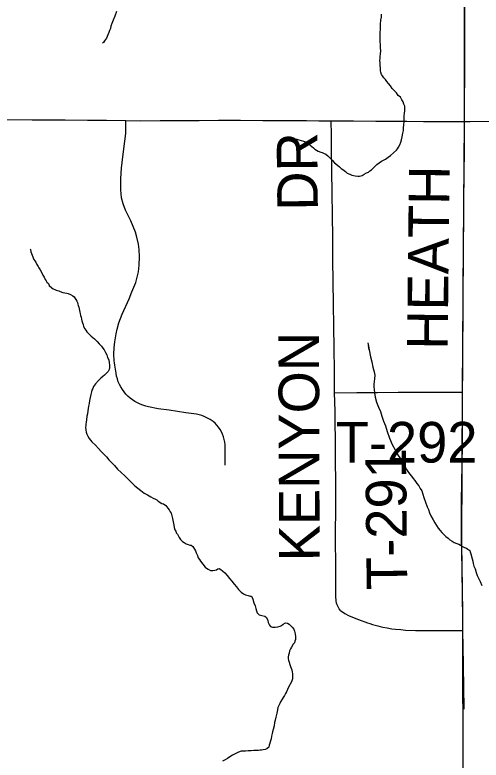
# Model space of a CAD drawing. Extents: x 103424 to 290657, y 38711 to 110967.
# Drawn here: x 116302 to 119767, y 74147 to 79687 of the extents above; entities that cross this region are included whole.
import ezdxf

# ---------------------------------------------------------------- set-up
doc = ezdxf.new("R2010")
doc.units = 0
for name, color, linetype in [('GM_X_Corporation', 7, 'Continuous'), ('GM_X_Minor_River', 7, 'Continuous'), ('GM_X_Township_Road', 7, 'Continuous'), ('GM_X_Township_Road_Text', 7, 'Continuous'), ('GM_X_US_Route', 7, 'Continuous'), ('SC_Scratch1', 7, 'Continuous')]:
    doc.layers.add(name, color=color, linetype=linetype)

msp = doc.modelspace()

# ---------------------------------------------------------------- linework, layer by layer
at = {"layer": 'GM_X_Corporation'}
for points in [[(103423.7, 96534.8), (103423.7, 70904.9), (107977, 70917.3), (117928.9, 70934.4), (117946.9, 70934.9), (119688.2, 70990.2), (119635, 74016.7), (119631.7, 75117.1), (119628.6, 75451.2), (119621.3, 75805.1), (119622.8, 76073.8), (119627.2, 76341.1), (119628.6, 76885.8), (119631.6, 77245.6), (119644.2, 78899.8), (119644.5, 79431.3), (119642.9, 80216.4), (119641.6, 80653.5), (119641.6, 81200.9), (119640.3, 81697.7), (119639, 82590.1), (119639, 83128.3), (119639, 84504.6), (119641.6, 85722.3)], [(119688.2, 70990.2), (119635, 74016.7), (119631.7, 75117.1), (119628.6, 75451.2), (119621.3, 75805.1), (119622.8, 76073.8), (119627.2, 76341.1), (119628.6, 76885.8), (119631.6, 77245.6), (119644.2, 78899.8), (119644.5, 79431.3), (119642.9, 80216.4), (119641.6, 80653.5), (119641.6, 81200.9), (119640.3, 81697.7), (119639, 82590.1), (119639, 83128.3), (119639, 84504.6), (119641.6, 85722.3)]]:
    msp.add_lwpolyline(points, dxfattribs=at)
at = {"layer": 'GM_X_Minor_River'}
for points in [[(117056.7, 79712), (117045, 79677.5), (117033.3, 79647.1), (117023.5, 79622.8), (117015.6, 79602.5), (117011.8, 79586.3), (117005.9, 79570.1), (117000, 79555.9), (116992.1, 79537.6), (116982.3, 79513.3), (116968.4, 79495), (116960.5, 79480.7), (116954.5, 79476.6)], [(119020.6, 79464.9), (119018.3, 79489.1), (119016, 79519.4), (119018.9, 79618.4), (119022.6, 79646.7), (119026.3, 79671), (119026.1, 79691.2)], [(118338.2, 78765.9), (118350.1, 78767.4), (118396.7, 78761.8), (118412.8, 78757.9), (118431.1, 78754), (118447.3, 78748.2), (118461.5, 78742.2), (118471.7, 78736.3), (118485.9, 78728.3), (118498.1, 78718.3), (118510.4, 78708.4), (118522.6, 78698.4), (118532.8, 78688.4), (118545, 78680.4), (118557.2, 78674.5), (118575.5, 78666.6), (118585.6, 78664.7), (118595.8, 78658.7), (118614, 78650.8), (118628.3, 78638.9), (118644.6, 78622.9), (118661, 78606.9), (118677.4, 78586.8), (118699.8, 78568.9), (118714.1, 78556.9), (118726.3, 78544.9), (118738.6, 78536.9), (118748.7, 78531), (118758.9, 78523), (118771.2, 78511), (118791.5, 78503.1), (118805.7, 78495.2), (118819.8, 78493.3), (118832, 78489.4), (118850.2, 78487.5), (118864.3, 78487.7), (118874.4, 78489.8), (118884.5, 78493.9), (118898.5, 78502.2), (118916.6, 78512.4), (118930.6, 78518.6), (118940.6, 78526.8), (118952.6, 78535), (118968.6, 78549.3), (118992.6, 78573.8), (119026.6, 78598.4), (119056.7, 78614.8), (119076.8, 78629.2), (119094.8, 78641.5), (119138.8, 78680.3), (119146.8, 78690.5), (119154.7, 78702.7), (119162.6, 78720.9), (119170.4, 78741.2), (119176.3, 78757.4), (119180.1, 78779.7), (119185.8, 78808), (119191.6, 78828.3), (119191.4, 78846.5), (119193.2, 78868.7), (119194.9, 78895), (119196.7, 78909.1), (119196.6, 78923.3), (119196.4, 78937.4), (119198.2, 78955.6), (119200, 78973.8), (119199.8, 78990), (119199.6, 79008.1), (119193.4, 79024.2), (119187.1, 79040.3), (119178.9, 79054.4), (119168.6, 79074.5), (119152.2, 79088.5), (119137.9, 79106.5), (119123.6, 79122.5), (119107.2, 79140.5), (119092.8, 79160.6), (119078.5, 79176.6), (119066.2, 79192.6), (119055.9, 79206.7), (119043.7, 79218.7), (119035.4, 79232.7), (119027.2, 79244.8), (119023, 79260.9), (119020.9, 79271), (119020.7, 79283.1), (119018.6, 79295.2), (119018.4, 79307.3), (119016.3, 79319.4), (119016.1, 79331.5), (119015.9, 79347.7), (119017.8, 79361.8), (119017.6, 79378), (119019.4, 79396.2), (119021.1, 79420.4), (119020.9, 79442.7), (119020.6, 79464.9)], [(116414.8, 77946.2), (116418.9, 77942.2), (116421.1, 77926), (116431.5, 77899.9), (116444, 77869.7), (116458.4, 77847.6), (116466.6, 77831.5), (116474.9, 77817.5), (116481.1, 77805.4), (116489.3, 77791.4), (116499.6, 77773.3), (116510, 77753.2), (116520.3, 77737.1), (116528.5, 77721.1), (116534.7, 77711), (116540.9, 77701), (116551.1, 77689), (116557.3, 77674.9), (116575.7, 77656.9), (116587.9, 77650.9), (116598.1, 77645), (116608.2, 77641), (116628.5, 77635.2), (116638.6, 77631.2), (116658.9, 77623.4), (116673.1, 77621.5), (116689.2, 77617.6), (116699.4, 77615.7), (116715.6, 77607.8), (116731.9, 77597.8), (116744.1, 77589.9), (116762.6, 77559.8), (116766.8, 77547.7), (116771, 77537.6), (116773.1, 77525.5), (116777.3, 77513.5), (116779.5, 77501.4), (116783.6, 77489.3), (116785.8, 77477.2), (116787.9, 77467.1), (116790.1, 77453), (116794.3, 77438.9), (116796.5, 77424.8), (116800.7, 77412.7), (116804.9, 77398.6), (116809.1, 77386.5), (116813.3, 77370.4), (116821.6, 77354.3), (116829.8, 77342.3), (116838, 77330.2), (116846.2, 77320.2), (116868.7, 77298.2), (116880.9, 77288.2), (116893.1, 77278.3), (116903.3, 77268.3), (116913.5, 77258.3), (116929.9, 77242.3), (116946.3, 77224.3), (116956.5, 77210.2), (116966.8, 77196.2), (116975.1, 77178.1), (116985.4, 77160), (116991.7, 77139.9), (117000, 77121.8), (117004.2, 77101.6), (117006.4, 77085.5), (117006.6, 77073.4), (117006.7, 77063.3), (117002.8, 77051.1), (116994.9, 77036.9), (116982.9, 77022.6), (116969, 77008.3), (116954.9, 76998.1), (116940.9, 76985.8), (116922.9, 76969.5), (116901, 76945), (116895.1, 76934.9), (116887.1, 76924.7), (116881.2, 76910.5), (116875.3, 76898.3), (116871.4, 76884.2), (116865.6, 76863.9), (116861.8, 76843.7), (116858, 76821.4), (116854.3, 76797.1), (116850.4, 76778.9), (116846.6, 76760.7), (116844.8, 76742.5), (116841, 76722.2), (116837.2, 76704), (116833.4, 76677.7), (116831.6, 76659.5), (116829.8, 76645.4), (116829.9, 76631.2), (116828, 76621.1), (116830.3, 76598.9), (116832.5, 76584.8), (116836.7, 76570.7), (116845, 76554.6), (116855.3, 76538.6), (116873.7, 76512.5)], [(118925.1, 77250), (118935.8, 77197.6), (118929.4, 77227.8), (118935.8, 77197.6), (118946.5, 77145.2), (118955.1, 77106.9), (118963.6, 77068.6), (118972.1, 77034.3), (118976.4, 77008.1), (118974.7, 76981.8), (118972.9, 76961.6), (118971.1, 76941.4), (118969.3, 76921.2), (118971.6, 76901), (118973.9, 76876.8), (118980.3, 76844.5), (118990.8, 76808.3), (119005.4, 76772.1), (119019.9, 76737.9), (119030.4, 76703.6), (119043, 76667.4), (119057.5, 76631.2), (119070.1, 76588.9), (119086.8, 76540.6), (119107.6, 76492.3), (119128.2, 76454.1), (119146.8, 76420), (119167.4, 76385.9), (119177.8, 76363.7), (119186, 76347.7), (119196.3, 76333.6), (119204.5, 76321.6), (119212.7, 76307.5), (119223, 76291.5), (119235.3, 76275.4), (119249.7, 76257.4), (119262, 76241.4), (119274.3, 76225.3), (119288.7, 76203.2), (119305, 76185.2), (119315.4, 76167.1), (119325.7, 76149.1), (119334, 76124.9), (119342.4, 76098.7), (119365.4, 76030.3), (119375.7, 76010.2), (119384.1, 75986), (119394.5, 75963.9), (119411, 75933.8), (119423.3, 75911.7), (119435.7, 75891.6), (119448, 75871.5), (119462.4, 75853.5), (119476.7, 75839.5), (119491, 75825.5), (119505.3, 75809.5), (119521.6, 75797.5), (119535.9, 75785.6), (119552.1, 75775.6), (119568.4, 75765.7), (119586.7, 75757.8), (119600.9, 75751.9), (119615.1, 75743.9), (119629.4, 75736), (119643.6, 75728), (119659.8, 75722.1), (119670, 75716.2), (119684.2, 75706.2), (119686.4, 75696.1), (119690.6, 75680), (119701.1, 75643.8), (119705.4, 75625.6), (119709.6, 75609.5), (119713.9, 75589.4), (119722.2, 75569.2), (119730.6, 75543.1), (119738.9, 75518.9), (119749.2, 75498.8), (119759.6, 75474.7), (119772.1, 75446.5)], [(116873.7, 76512.5), (116900.3, 76488.5), (116922.8, 76464.5), (116943.2, 76442.5), (116963.6, 76422.5), (116984.1, 76402.5), (117000.5, 76380.4), (117020.9, 76360.4), (117043.4, 76336.4), (117065.9, 76310.4), (117092.4, 76286.4), (117119, 76260.4), (117151.7, 76228.4), (117174.2, 76206.4), (117192.6, 76186.4), (117215, 76168.4), (117237.4, 76150.5), (117263.9, 76132.6), (117288.3, 76118.7), (117312.7, 76104.8), (117330.9, 76094.9), (117347.2, 76087), (117357.4, 76081), (117367.6, 76073), (117394, 76055.1), (117406.2, 76051.2), (117424.5, 76039.2), (117438.8, 76021.2), (117449.1, 76007.2), (117457.3, 75993.1), (117463.5, 75983.1), (117469.8, 75962.9), (117474.1, 75942.8), (117478.4, 75918.6), (117482.7, 75894.4), (117487, 75876.2), (117491.2, 75860.1), (117497.4, 75848.1), (117501.5, 75838), (117509.7, 75828), (117515.9, 75815.9), (117524.2, 75801.9), (117534.4, 75787.8), (117548.8, 75771.8), (117561, 75763.9), (117575.2, 75753.9), (117591.4, 75750), (117601.6, 75746.1), (117611.7, 75744.2), (117625.9, 75736.2), (117636.3, 75716.1), (117644.5, 75702.1), (117650.7, 75688), (117659, 75667.9), (117665.3, 75651.8), (117673.5, 75637.7), (117681.7, 75625.7), (117716.6, 75581.6), (117726.8, 75573.6), (117739, 75565.6), (117757.3, 75555.7), (117773.4, 75555.9), (117787.5, 75558.1), (117801.6, 75562.2), (117811.6, 75568.4), (117821.7, 75570.5), (117831.9, 75564.6), (117846.1, 75554.6), (117862.5, 75538.6), (117878.9, 75518.6), (117897.3, 75496.5), (117915.7, 75476.5), (117932.1, 75454.5), (117948.5, 75434.4), (117964.9, 75416.4), (117983.3, 75396.4), (118001.6, 75382.4), (118015.8, 75376.5), (118036.1, 75370.7), (118050.3, 75366.8), (118060.4, 75364.8), (118070.7, 75342.7), (118079.1, 75316.5), (118087.5, 75294.4), (118093.7, 75274.3), (118098, 75258.2), (118102.2, 75242), (118118.5, 75228.1), (118138.8, 75222.2), (118161.1, 75216.4), (118171.3, 75208.4), (118181.6, 75186.3), (118185.8, 75170.1), (118194.1, 75150), (118202.4, 75140), (118216.5, 75136.1), (118236.7, 75136.3), (118256.9, 75138.5), (118273, 75142.7), (118283.1, 75146.9), (118297, 75159.1)], [(118297, 75159.1), (118313.1, 75167.4), (118329.3, 75165.5), (118341.5, 75157.6), (118351.7, 75147.6), (118364, 75135.6), (118376.2, 75121.5), (118380.5, 75105.4), (118384.8, 75085.3), (118389, 75063.1), (118387.2, 75044.9), (118383.3, 75032.7), (118379.5, 75018.6), (118371.5, 75008.4), (118357.6, 74988), (118349.7, 74973.8), (118343.8, 74959.6), (118340, 74941.4), (118336.1, 74927.2), (118334.2, 74915.1), (118334.4, 74900.9), (118336.5, 74890.9), (118340.7, 74874.8), (118347, 74858.7), (118351.2, 74842.5), (118355.4, 74830.5), (118359.6, 74818.4), (118363.8, 74800.2), (118366, 74790.2), (118366.1, 74776), (118366.3, 74763.9), (118364.4, 74751.8), (118358.6, 74729.5), (118336.8, 74688.9), (118328.9, 74672.6), (118321.1, 74654.4), (118313.1, 74642.2), (118305.2, 74628), (118297.3, 74611.7), (118289.4, 74599.5), (118277.5, 74581.2), (118271.6, 74569.1), (118263.7, 74552.8), (118257.8, 74538.6), (118254, 74520.4), (118248.2, 74496.1), (118242.5, 74465.7), (118236.7, 74445.5), (118232.8, 74427.3), (118229.1, 74401), (118221.3, 74374.6), (118217.5, 74356.4), (118213.6, 74344.3), (118209.8, 74326), (118206, 74305.8), (118202.1, 74291.6), (118198.3, 74273.4), (118192.4, 74257.2), (118190.5, 74243), (118174.5, 74230.7), (118162.5, 74226.6), (118148.3, 74224.4), (118136.3, 74222.3), (118126.1, 74222.2), (118112, 74220), (118095.9, 74217.8), (118077.7, 74217.7), (118057.6, 74215.4), (118035.4, 74215.2), (118017.2, 74215), (117999, 74214.9), (117982.9, 74212.7), (117964.8, 74206.4), (117918.6, 74183.8), (117900.5, 74171.5), (117882.5, 74159.2), (117864.5, 74148.9), (117846.4, 74138.6)]]:
    msp.add_lwpolyline(points, dxfattribs=at)
at = {"layer": 'GM_X_Township_Road'}
for points in [[(119644.5, 78894.7), (119645, 79059.8), (119645.4, 79224.9), (119645.9, 79373.4), (119646.3, 79522), (119645.9, 79687), (119645.6, 79852.1), (119644.6, 80290.5), (119644.2, 80455.6), (119643.7, 80620.6), (119643.3, 80785.7), (119642.8, 80950.8), (119642.1, 81199.9), (119640.9, 81860.2), (119638.6, 83127.2), (119637.6, 84501.8), (119638.3, 84666.9), (119639.1, 84831.9), (119639.6, 84957.7)], [(117865.9, 76339.5), (117864.6, 76492.1), (117862.3, 76511.9), (117858.3, 76531.4), (117853, 76550.7), (117846, 76569.3), (117837.7, 76587.4), (117827.8, 76604.8), (117816.8, 76621.3), (117804.2, 76636.9), (117790.6, 76651.5), (117776, 76664.9), (117753.9, 76678.5), (117709.7, 76700.4), (117690.7, 76708.6), (117650.9, 76717.9), (117572.7, 76730), (117449.8, 76748.7), (117367.5, 76759.2), (117296, 76774), (117274.6, 76778.7), (117253.8, 76785), (117233.6, 76792.8), (117213.7, 76802), (117194.9, 76812.6), (117176.5, 76824.6), (117159.4, 76837.9), (117143, 76852.4), (117127.9, 76868.1), (117113.8, 76884.8), (117101.3, 76902.5), (117089.7, 76921), (117079.6, 76940.4), (117071.1, 76960.4), (117064, 76981), (117058.5, 77002.1), (117054.5, 77023.5), (117045.2, 77083.2), (117042.9, 77099.4), (117041.2, 77115.6), (117039.7, 77131.9), (117038.7, 77148.2), (117037.9, 77164.5), (117041.4, 77213), (117045.1, 77256.8), (117054, 77316.9), (117061.7, 77350.1), (117075.5, 77398.4), (117099.8, 77462.8), (117151.3, 77576.8), (117172.4, 77627.9), (117200, 77697.2), (117210.9, 77737), (117220.3, 77777.5), (117225.5, 77825.8), (117228, 77888.2), (117225.1, 77942.6), (117220.3, 77983.5), (117209.3, 78035.4), (117199.6, 78071.5), (117182.5, 78113.7), (117164.3, 78155.5), (117124.6, 78234.9), (117106.7, 78283.2), (117094.6, 78327), (117089.3, 78386.2), (117089.7, 78469.8), (117095.8, 78546.4), (117099.8, 78590.6), (117107.1, 78651.4), (117118.9, 78749.2), (117126.2, 78806.3), (117127, 78875.3), (117126.5, 78901.6)], [(118721.7, 75260.3), (118712.7, 75270.7), (118705.2, 75286.7), (118698.6, 75300.4), (118692.9, 75315.1), (118690, 75332.1), (118688.2, 75363.2), (118687.7, 75528.3), (118686.2, 75851.7), (118686.9, 75997.6), (118687.7, 76143.5), (118682.8, 76741.3), (118678.8, 76877.1), (118676.8, 77042.2), (118674.7, 77207.2), (118672.7, 77372.3), (118670.6, 77537.4), (118668.6, 77702.4), (118666.6, 77867.5), (118664.6, 78032.6), (118662.5, 78197.6), (118660.5, 78362.7), (118658.5, 78527.8), (118656.4, 78692.8), (118655.2, 78796), (118653.9, 78899.2)], [(119623.8, 75841.9), (119624.5, 75964.3), (119625.6, 76129.4), (119626.4, 76247.5), (119627.2, 76365.6), (119628, 76474.6), (119628.9, 76583.6), (119629.3, 76687.7), (119630.2, 76883), (119631.4, 77048.1), (119632.1, 77148.5), (119632.8, 77248.9), (119633.6, 77413.9), (119634.3, 77569), (119634.9, 77724.1), (119636.3, 77889.1), (119637.5, 78035), (119638.7, 78180.9), (119640.1, 78346), (119641.4, 78511.1), (119642.8, 78676.1), (119643.6, 78771.4), (119644.4, 78866.6), (119644.5, 78894.7)], [(118678.8, 76877.1), (118843.9, 76879.1), (118998, 76881), (119152.1, 76882.9), (119630.2, 76883)], [(119636.2, 74846.5), (119636.1, 74857.2), (119634.4, 74983.9), (119632.6, 75110.7), (119631, 75245.6), (119629, 75410.7), (119627.7, 75519.2), (119626.4, 75627.7), (119624.9, 75713.5), (119623.5, 75799.3), (119623.8, 75841.9)], [(118721.7, 75260.3), (118754.3, 75236.7), (118780.7, 75223), (118823.4, 75204.5), (118855.4, 75191.9), (118921.9, 75168.5), (118941, 75162), (118960.2, 75155.8), (118979.3, 75150.1), (118999, 75144.7), (119018.3, 75139.7), (119038, 75134.9), (119069.7, 75130.4), (119104, 75124.1), (119130.2, 75121.4), (119171.5, 75117.4), (119204.4, 75113.5), (119280.3, 75111.1), (119632.6, 75110.7)], [(119640.6, 74527.1), (119638.3, 74692.1), (119636.2, 74846.5)]]:
    msp.add_lwpolyline(points, dxfattribs=at)
at = {"layer": 'GM_X_US_Route'}
for points in [[(119644.5, 78894.7), (119686.8, 78895.3), (119846.6, 78896.9), (120001.7, 78900.3), (120156.7, 78903.7), (120321.8, 78905.8), (120433.7, 78907.3), (120545.6, 78908.8), (120666.1, 78911.1), (120788.8, 78913.7), (120953.9, 78915.9), (121053.7, 78917.3), (121153.6, 78918.6), (121318.7, 78921.1), (121483.7, 78923.6), (121591.9, 78925.2), (121700, 78926.8), (121860.1, 78930.5), (122004.4, 78934.4), (122101.1, 78935.2), (122140.6, 78935.7), (122281.9, 78937.5), (122360.5, 78938.5)], [(115132.9, 78910), (116430.7, 78907.5), (116553.7, 78906.9), (116676.7, 78906.3), (116841.8, 78904.6), (116984.2, 78903.1), (117126.5, 78901.6), (117236.8, 78900.3), (117382.2, 78901), (117527.7, 78901.7), (117671.3, 78902.7), (117815, 78903.8), (117980, 78903), (118145.1, 78902.2), (118308, 78901.4), (118470.8, 78900.6), (118562.4, 78899.9), (118653.9, 78899.2), (118819, 78898.5), (118984, 78897.7), (119100.1, 78897.2), (119216.1, 78896.7), (119339.4, 78895.5), (119462.7, 78894.2), (119644.5, 78894.7)]]:
    msp.add_lwpolyline(points, dxfattribs=at)
at = {"layer": 'SC_Scratch1'}
for points in [[(119644.5, 78894.7), (119686.8, 78895.3), (119846.6, 78896.9), (120001.7, 78900.3), (120156.7, 78903.7), (120321.8, 78905.8), (120433.7, 78907.3), (120545.6, 78908.8), (120666.1, 78911.1), (120788.8, 78913.7), (120953.9, 78915.9), (121053.7, 78917.3), (121153.6, 78918.6), (121318.7, 78921.1), (121483.7, 78923.6), (121591.9, 78925.2), (121700, 78926.8), (121860.1, 78930.5), (122004.4, 78934.4), (122101.1, 78935.2), (122140.6, 78935.7), (122281.9, 78937.5), (122360.5, 78938.5)], [(115132.9, 78910), (116430.7, 78907.5), (116553.7, 78906.9), (116676.7, 78906.3), (116841.8, 78904.6), (116984.2, 78903.1), (117126.5, 78901.6), (117236.8, 78900.3), (117382.2, 78901), (117527.7, 78901.7), (117671.3, 78902.7), (117815, 78903.8), (117980, 78903), (118145.1, 78902.2), (118308, 78901.4), (118470.8, 78900.6), (118562.4, 78899.9), (118653.9, 78899.2), (118819, 78898.5), (118984, 78897.7), (119100.1, 78897.2), (119216.1, 78896.7), (119339.4, 78895.5), (119462.7, 78894.2), (119644.5, 78894.7)]]:
    msp.add_lwpolyline(points, dxfattribs=at)

# ---------------------------------------------------------------- texts
at = {"layer": 'GM_X_Township_Road_Text'}
for s, rotation, p in [('DR', 90.4937, (118554.4, 78232.6)), ('HEATH', 89.394, (119518.9, 77196.8)), ('KENYON', 90.1622, (118567.6, 75625.4)), ('T-292', 0, (118686.4, 76359.3)), ('T-291', 90.5622, (119219.1, 75413.4))]:
    msp.add_text(s, height=301.87, rotation=rotation, dxfattribs=at).set_placement(p)

doc.saveas('drawing.dxf')
